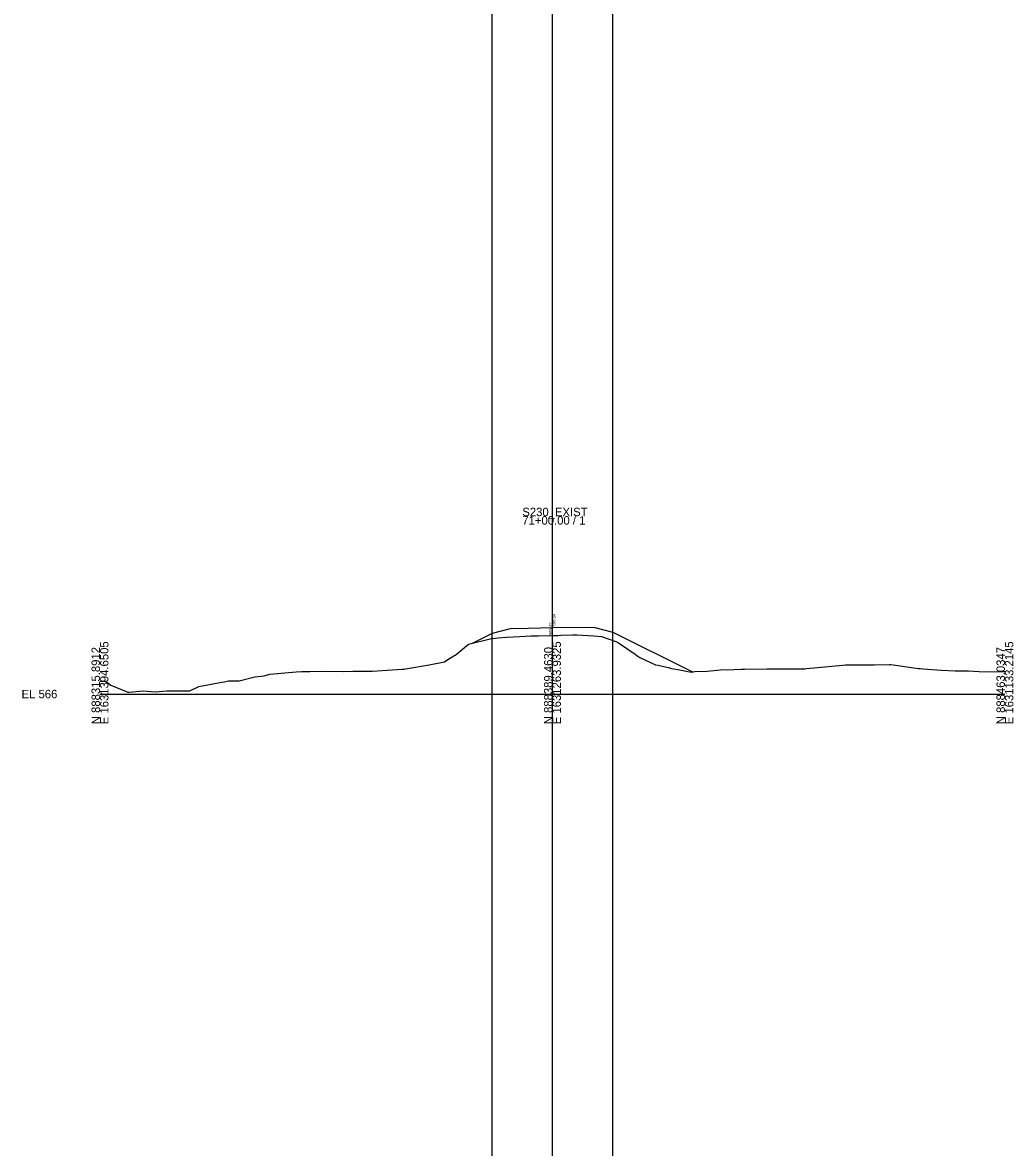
# Model space of a CAD drawing. Extents: x 1631115 to 1631443, y 885974 to 892071.
# Drawn here: x 1631114.8 to 1631443.3, y 889833.3 to 890206.3 of the extents above; entities that cross this region are included whole.
import ezdxf

# ---------------------------------------------------------------- set-up
doc = ezdxf.new("R2010")
doc.units = 0
for name, color, linetype in [('Default', 7, 'Continuous'), ('RD_GPK_XS_Cell', 7, 'Continuous'), ('RD_XS_EarthShd', 7, 'Continuous'), ('RD_XS_ExGround', 7, 'Continuous'), ('RD_XS_Pave', 7, 'Continuous'), ('RD_XS_TieSlope', 7, 'Continuous'), ('RD_XS_TX_Elev_EX', 7, 'Continuous'), ('RD_XS_TX_Elev_PR', 7, 'Continuous')]:
    doc.layers.add(name, color=color, linetype=linetype)

msp = doc.modelspace()

# ---------------------------------------------------------------- linework, layer by layer
at = {"layer": 'Default'}
for p, q in [((1631270.47, 885983.65), (1631270.47, 892068.63)), ((1631290.47, 885983.65), (1631290.47, 892068.63)), ((1631310.47, 885983.65), (1631310.47, 892068.63))]:
    msp.add_line(p, q, dxfattribs=at)
at = {"layer": 'RD_GPK_XS_Cell'}
for p, q in [((1631290.47, 889983.65), (1631290.47, 890042.64)), ((1631140.47, 889983.65), (1631290.47, 889983.65)), ((1631290.47, 889983.65), (1631440.47, 889983.65))]:
    msp.add_line(p, q, dxfattribs=at)
at = {"layer": 'RD_XS_EarthShd'}
for p, q in [((1631278.47, 890005.45), (1631276.47, 890005.29)), ((1631302.47, 890005.88), (1631304.47, 890005.72))]:
    msp.add_line(p, q, dxfattribs=at)
at = {"layer": 'RD_XS_ExGround'}
msp.add_lwpolyline([(1631140.47, 889987.85), (1631142.3, 889987.88), (1631144.08, 889986.6), (1631149.7, 889984.28), (1631150.07, 889984.28), (1631154.73, 889984.73), (1631158.75, 889984.34), (1631162.63, 889984.76), (1631170.29, 889984.71), (1631173.22, 889986.19), (1631180.89, 889987.56), (1631181.74, 889987.68), (1631183.12, 889988.02), (1631186.6, 889987.99), (1631191.79, 889989.35), (1631194.93, 889989.65), (1631196.8, 889990.28), (1631205.56, 889990.98), (1631207.35, 889991.17), (1631210, 889991.19), (1631215.82, 889991.2), (1631221.34, 889991.16), (1631224.32, 889991.22), (1631230.72, 889991.26), (1631240.65, 889991.89), (1631241.3, 889991.94), (1631241.74, 889992), (1631249.56, 889993.31), (1631254.63, 889994.38), (1631255.47, 889994.88), (1631257.8, 889996.36), (1631258.19, 889996.59), (1631258.53, 889996.73), (1631262.63, 890000.17), (1631269.82, 890001.92), (1631272.49, 890002.28), (1631275.23, 890002.54), (1631279.66, 890002.74), (1631283.42, 890002.95), (1631284.44, 890002.94), (1631285.73, 890002.98), (1631290.47, 890003.07), (1631292.25, 890003.11), (1631293.23, 890003.16), (1631297.28, 890003.27), (1631298.57, 890003.31), (1631304.24, 890002.99), (1631306.77, 890002.73), (1631311.44, 890001.07), (1631312.36, 890000.67), (1631317.9, 889996.85), (1631318.39, 889996.41), (1631319.41, 889995.8), (1631324.65, 889993.39), (1631325.47, 889993.21), (1631327.84, 889992.71), (1631328.92, 889992.41), (1631329.97, 889992.16), (1631332.73, 889991.69), (1631335.37, 889991.17), (1631336.58, 889990.93), (1631337.71, 889991.11), (1631341.81, 889991.28), (1631346.15, 889991.67), (1631350.67, 889991.8), (1631353.06, 889991.91), (1631354.17, 889991.88), (1631361.55, 889992.03), (1631361.85, 889992.03), (1631364.19, 889991.98), (1631373.41, 889992.04), (1631374.14, 889991.98), (1631374.68, 889992.13), (1631377.11, 889992.36), (1631386.72, 889993.19), (1631387.66, 889993.34), (1631389.38, 889993.39), (1631390.61, 889993.34), (1631394.61, 889993.38), (1631397.14, 889993.33), (1631402.26, 889993.44), (1631402.66, 889993.43), (1631411.79, 889992.18), (1631412.4, 889992.08), (1631413.38, 889991.99), (1631419.47, 889991.56), (1631423.96, 889991.37), (1631428.36, 889991.32), (1631431.89, 889991.14), (1631436.54, 889991.06), (1631439.02, 889991.12), (1631440.47, 889991.09)], dxfattribs=at)
at = {"layer": 'RD_XS_Pave'}
for p, q in [((1631278.47, 890005.45), (1631290.47, 890005.69)), ((1631290.47, 890005.69), (1631302.47, 890005.88))]:
    msp.add_line(p, q, dxfattribs=at)
at = {"layer": 'RD_XS_TieSlope'}
for p, q in [((1631270.47, 890003.79), (1631263.81, 890000.46)), ((1631276.47, 890005.29), (1631270.47, 890003.79)), ((1631304.47, 890005.72), (1631310.47, 890004.22)), ((1631310.47, 890004.22), (1631336.93, 889990.99))]:
    msp.add_line(p, q, dxfattribs=at)

# ---------------------------------------------------------------- texts
at = {"layer": 'RD_GPK_XS_Cell'}
for s, p in [('S230_EXIST', (1631280.47, 890042.64)), ('71+00.00 / 1', (1631280.47, 890039.84)), ('EL 566', (1631114.47, 889982.25))]:
    msp.add_text(s, height=2.8, dxfattribs=at).set_placement(p)
for s, p in [('E 1631394.6505', (1631143.27, 889973.65)), ('E 1631263.9325', (1631293.27, 889973.65)), ('E 1631133.2145', (1631443.27, 889973.65)), ('N 888315.8912', (1631140.47, 889973.65)), ('N 888389.4630', (1631290.47, 889973.65)), ('N 888463.0347', (1631440.47, 889973.65))]:
    msp.add_text(s, height=2.8, rotation=90, dxfattribs=at).set_placement(p)
at = {"layer": 'RD_XS_TX_Elev_EX'}
msp.add_text('585.42', height=1, rotation=90, dxfattribs=at).set_placement((1631290.37, 890003.17))
at = {"layer": 'RD_XS_TX_Elev_PR'}
msp.add_text(' 588.04', height=1, rotation=90, dxfattribs=at).set_placement((1631291.47, 890005.69))

doc.saveas('drawing.dxf')
